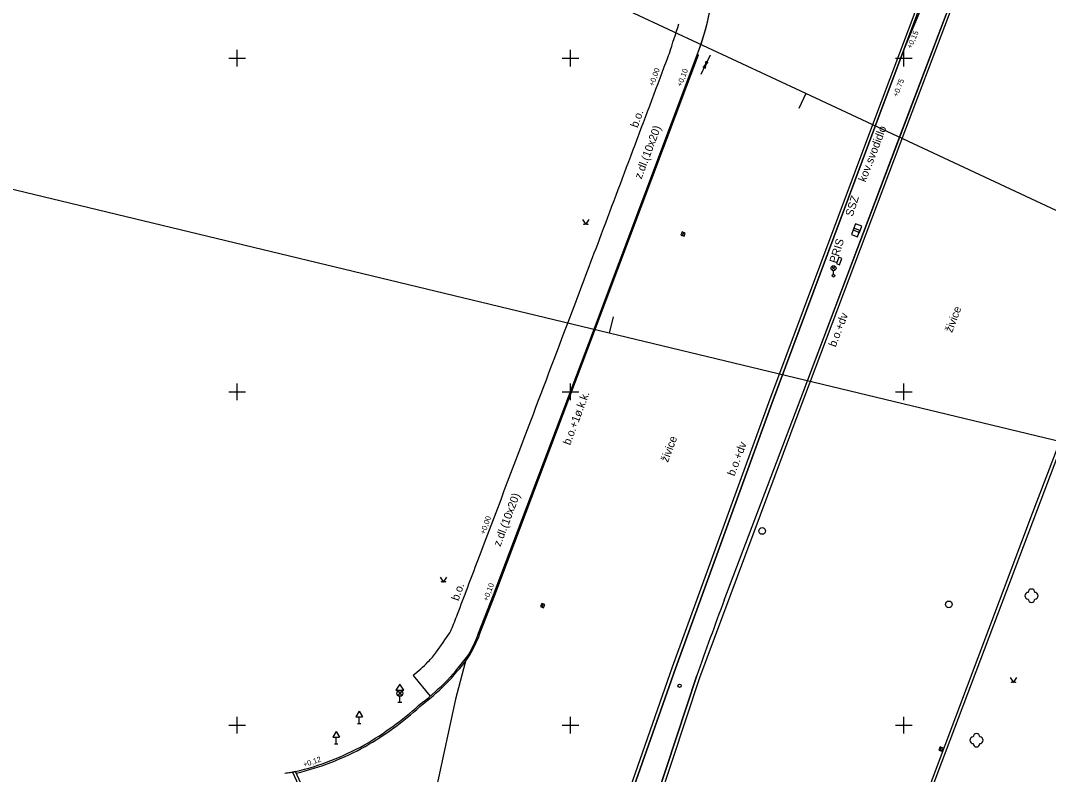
# Model space of a CAD drawing. Extents: x -599151 to -598424, y -1163476 to -1161924.
# Drawn here: x -598766.2 to -598689.2, y -1162728.7 to -1162672.2 of the extents above; entities that cross this region are included whole.
import ezdxf

# ---------------------------------------------------------------- set-up
doc = ezdxf.new("R2010")
doc.units = 0
for name, color, linetype in [('Vrstva 1', 7, 'Continuous'), ('Vrstva 14', 7, 'Continuous'), ('Vrstva 19', 7, 'Continuous'), ('Vrstva 21', 7, 'Continuous'), ('Vrstva 23', 7, 'Continuous'), ('Vrstva 25', 7, 'Continuous'), ('Vrstva 29', 7, 'Continuous'), ('Vrstva 44', 7, 'Continuous'), ('Vrstva 49', 7, 'Continuous'), ('Vrstva 50', 7, 'Continuous'), ('Vrstva 62', 7, 'Continuous'), ('Vrstva 63', 7, 'Continuous'), ('Vrstva 7', 7, 'Continuous')]:
    doc.layers.add(name, color=color, linetype=linetype)

msp = doc.modelspace()

# ---------------------------------------------------------------- linework, layer by layer
at = {"layer": 'Vrstva 1'}
for p, q in [((-598707.361, -1162677.641), (-598774.638, -1162646.226)), ((-598707.361, -1162677.641), (-598707.89, -1162678.774)), ((-598640.084, -1162709.057), (-598707.36, -1162677.641)), ((-598722.107, -1162695.603), (-598794.299, -1162678.242)), ((-598721.815, -1162694.387), (-598722.107, -1162695.603)), ((-598649.916, -1162712.964), (-598722.107, -1162695.603))]:
    msp.add_line(p, q, dxfattribs=at)
at = {"layer": 'Vrstva 14'}
for points in [[(-598724.104, -1162687.095), (-598723.854, -1162687.47), (-598723.604, -1162687.095)], [(-598734.771, -1162713.895), (-598734.521, -1162714.27), (-598734.271, -1162713.895)], [(-598692.032, -1162721.429), (-598691.782, -1162721.804), (-598691.532, -1162721.429)]]:
    msp.add_lwpolyline(points, dxfattribs=at)
for centre, radius in [((-598723.979, -1162687.445), 0.025), ((-598723.729, -1162687.445), 0.025), ((-598734.646, -1162714.245), 0.025), ((-598734.396, -1162714.245), 0.025), ((-598690.43, -1162715.29), 0.00025), ((-598691.907, -1162721.779), 0.025), ((-598691.657, -1162721.779), 0.025), ((-598694.56, -1162726.131), 0.00025)]:
    msp.add_circle(centre, radius, dxfattribs=at)
for centre, start, end in [((-598690.68, -1162715.29), 89.99999, 269.99999), ((-598690.43, -1162715.04), 0, 179.99999), ((-598690.18, -1162715.29), 270, 89.99999), ((-598690.43, -1162715.54), 179.99999, 359.99999), ((-598694.81, -1162726.131), 89.99999, 269.99999), ((-598694.56, -1162725.881), 0, 179.99999), ((-598694.31, -1162726.131), 270, 89.99999), ((-598694.56, -1162726.381), 179.99999, 359.99999)]:
    msp.add_arc(centre, 0.25, start, end, dxfattribs=at)
at = {"layer": 'Vrstva 19'}
for p, q in [((-598740.85, -1162723.938), (-598741.1, -1162724.371)), ((-598741.1, -1162724.371), (-598740.6, -1162724.371)), ((-598740.85, -1162723.938), (-598740.6, -1162724.371)), ((-598740.85, -1162724.871), (-598740.85, -1162724.371)), ((-598740.975, -1162724.871), (-598740.725, -1162724.871)), ((-598742.58, -1162725.468), (-598742.83, -1162725.901)), ((-598742.83, -1162725.901), (-598742.33, -1162725.901)), ((-598742.58, -1162725.468), (-598742.33, -1162725.901)), ((-598742.58, -1162726.401), (-598742.58, -1162725.901)), ((-598742.705, -1162726.401), (-598742.455, -1162726.401))]:
    msp.add_line(p, q, dxfattribs=at)
at = {"layer": 'Vrstva 21'}
msp.add_lwpolyline([(-598695.78, -1162664.24), (-598699.97, -1162674.3), (-598702.11, -1162679.97), (-598709.91, -1162700.89), (-598717.13, -1162720.74), (-598723.5, -1162738.84), (-598727.94, -1162752.59), (-598729.98, -1162757.92), (-598744.45, -1162796.07), (-598751.7, -1162815.01), (-598765.52, -1162851.41), (-598773.26, -1162871.58), (-598779.91, -1162889.88), (-598781.91, -1162894.82), (-598784.85, -1162901.68), (-598795.29, -1162929.3), (-598803.04, -1162949.86), (-598814.6, -1162980.19)], dxfattribs=at)
at = {"layer": 'Vrstva 23'}
for p, q in [((-598703.624, -1162687.407), (-598703.803, -1162687.874)), ((-598703.157, -1162687.586), (-598703.624, -1162687.407)), ((-598703.764, -1162687.737), (-598703.943, -1162688.204)), ((-598703.943, -1162688.204), (-598703.476, -1162688.383)), ((-598703.803, -1162687.874), (-598703.336, -1162688.053)), ((-598703.297, -1162687.916), (-598703.764, -1162687.737)), ((-598703.476, -1162688.383), (-598703.297, -1162687.916)), ((-598703.336, -1162688.053), (-598703.157, -1162687.586))]:
    msp.add_line(p, q, dxfattribs=at)
msp.add_circle((-598716.82, -1162722.04), 0.125, dxfattribs=at)
at = {"layer": 'Vrstva 25'}
for p, q in [((-598716.604, -1162688.297), (-598716.516, -1162688.063)), ((-598727.134, -1162716.147), (-598727.046, -1162715.913)), ((-598697.265, -1162726.907), (-598697.175, -1162726.673))]:
    msp.add_line(p, q, dxfattribs=at)
for points in [[(-598716.487, -1162688.341), (-598716.399, -1162688.107), (-598716.633, -1162688.019), (-598716.721, -1162688.253)], [(-598727.017, -1162716.191), (-598726.929, -1162715.957), (-598727.163, -1162715.869), (-598727.251, -1162716.103)], [(-598697.148, -1162726.951), (-598697.059, -1162726.718), (-598697.292, -1162726.629), (-598697.381, -1162726.862)], [(-598741.558, -1162737.828), (-598741.4, -1162737.681), (-598745.63, -1162728.471), (-598745.836, -1162728.513)]]:
    msp.add_lwpolyline(points, close=True, dxfattribs=at)
for centre in [(-598710.63, -1162710.44), (-598696.64, -1162715.94)]:
    msp.add_circle(centre, 0.25, dxfattribs=at)
at = {"layer": 'Vrstva 29'}
for p, q in [((-598705.412, -1162690.869), (-598705.148, -1162690.605)), ((-598705.144, -1162690.868), (-598705.408, -1162690.603)), ((-598705.28, -1162691.2), (-598705.28, -1162690.925))]:
    msp.add_line(p, q, dxfattribs=at)
msp.add_lwpolyline([(-598704.832, -1162690.478), (-598704.654, -1162690.011), (-598704.888, -1162689.922), (-598705.066, -1162690.389)], close=True, dxfattribs=at)
for centre, radius in [((-598705.28, -1162690.738), 0.188), ((-598705.28, -1162691.3), 0.1)]:
    msp.add_circle(centre, radius, dxfattribs=at)
at = {"layer": 'Vrstva 44'}
for p, q in [((-598737.65, -1162722.43), (-598737.95, -1162722.774)), ((-598737.95, -1162722.43), (-598737.65, -1162722.774)), ((-598737.8, -1162723.28), (-598737.8, -1162722.83)), ((-598737.95, -1162723.28), (-598737.65, -1162723.28))]:
    msp.add_line(p, q, dxfattribs=at)
msp.add_lwpolyline([(-598738.1, -1162722.374), (-598737.5, -1162722.374), (-598737.8, -1162721.924), (-598738.1, -1162722.374)], dxfattribs=at)
msp.add_circle((-598737.8, -1162722.602), 0.228, dxfattribs=at)
at = {"layer": 'Vrstva 49'}
for p, q in [((-598714.54, -1162674.763), (-598714.869, -1162675.483)), ((-598715.198, -1162676.203), (-598714.869, -1162675.483)), ((-598715.046, -1162675.697), (-598714.869, -1162675.483)), ((-598714.869, -1162675.483), (-598714.915, -1162675.759)), ((-598714.869, -1162675.483), (-598714.824, -1162675.207)), ((-598714.692, -1162675.267), (-598714.869, -1162675.483))]:
    msp.add_line(p, q, dxfattribs=at)
at = {"layer": 'Vrstva 62'}
for p, q in [((-598750.625, -1162675), (-598749.375, -1162675)), ((-598750, -1162675.625), (-598750, -1162674.375)), ((-598725.625, -1162675), (-598724.375, -1162675)), ((-598725, -1162675.625), (-598725, -1162674.375)), ((-598700.625, -1162675), (-598699.375, -1162675)), ((-598700, -1162675.625), (-598700, -1162674.375)), ((-598750, -1162700.625), (-598750, -1162699.375)), ((-598725, -1162700.625), (-598725, -1162699.375)), ((-598700, -1162700.625), (-598700, -1162699.375)), ((-598750.625, -1162700), (-598749.375, -1162700)), ((-598725.625, -1162700), (-598724.375, -1162700)), ((-598700.625, -1162700), (-598699.375, -1162700)), ((-598750, -1162725.625), (-598750, -1162724.375)), ((-598725, -1162725.625), (-598725, -1162724.375)), ((-598700, -1162725.625), (-598700, -1162724.375)), ((-598750.625, -1162725), (-598749.375, -1162725)), ((-598725.625, -1162725), (-598724.375, -1162725)), ((-598700.625, -1162725), (-598699.375, -1162725))]:
    msp.add_line(p, q, dxfattribs=at)
at = {"layer": 'Vrstva 63'}
for points in [[(-598859.45, -1163096.65), (-598854.32, -1163084.15), (-598824.47, -1163005.5), (-598816.67, -1162984.98), (-598803.24, -1162949.74), (-598780.23, -1162889.28), (-598773.478, -1162871.463), (-598765.88, -1162851.33), (-598758.84, -1162832.8), (-598745.6, -1162798.16), (-598737.25, -1162776.15), (-598728.25, -1162752.5), (-598723.5, -1162738.84), (-598717.13, -1162720.74), (-598709.91, -1162700.89), (-598702.11, -1162679.97), (-598696.15, -1162664.13), (-598695.39, -1162662.07), (-598693.97, -1162658.31)], [(-598713.47, -1162715.62), (-598708.12, -1162701.56), (-598694.22, -1162664.8), (-598692.03, -1162658.97)], [(-598731.89, -1162718.09), (-598730.78, -1162715.22), (-598723.28, -1162695.43), (-598715.5, -1162674.74)], [(-598697.52, -1162728.69), (-598683.522, -1162691.742)], [(-598732.8, -1162719.93), (-598733.62, -1162723.04), (-598736.975, -1162738.546)], [(-598715.54, -1162721.28), (-598721.7, -1162739.99), (-598727.72, -1162758.34), (-598733.31, -1162775.48), (-598734.01, -1162777.52), (-598762.71, -1162852.94), (-598770.32, -1162872.91), (-598777.27, -1162891.31), (-598784.14, -1162909.43), (-598799.74, -1162950.34), (-598813.33, -1162986.07), (-598821.23, -1163006.93), (-598828.55, -1163026.09), (-598835.89, -1163045.37), (-598843.55, -1163065.41), (-598852.18, -1163085.13), (-598858.28, -1163096.77)]]:
    msp.add_lwpolyline(points, dxfattribs=at)
for centre, radius, start, end in [((-598733.303, -1162667.848), 19.091, 338.83707, 2.45527), ((-598468.093, -1162808.569), 262.391, 159.2533, 160.56931), ((-598739.805, -1162715.321), 8.385, 326.65376, 340.71545), ((-598851.716, -1162677.132), 162.587, 335.66863, 341.51174)]:
    msp.add_arc(centre, radius, start, end, dxfattribs=at)
at = {"layer": 'Vrstva 7'}
msp.add_line((-598736.81, -1162721.261), (-598735.53, -1162722.821), dxfattribs=at)
for points in [[(-598696.37, -1162664.06), (-598702.36, -1162680), (-598710.16, -1162700.82), (-598717.38, -1162720.66), (-598723.7, -1162738.77), (-598728.46, -1162752.352), (-598730.54, -1162757.75), (-598737.46, -1162776.08), (-598745, -1162795.86), (-598752.22, -1162814.82), (-598759.04, -1162832.74), (-598766.06, -1162851.25)], [(-598765.88, -1162851.33), (-598758.84, -1162832.8), (-598752, -1162814.9), (-598745.6, -1162798.16), (-598744.77, -1162795.95), (-598742.6, -1162790.26), (-598740.02, -1162783.45), (-598737.25, -1162776.15), (-598730.28, -1162757.84), (-598728.25, -1162752.5), (-598723.5, -1162738.84), (-598717.13, -1162720.74), (-598709.91, -1162700.89), (-598702.11, -1162679.97), (-598699.97, -1162674.3), (-598696.15, -1162664.13)], [(-598762.5, -1162853.02), (-598755.36, -1162834.29), (-598748.57, -1162816.46), (-598741.19, -1162797.06), (-598733.81, -1162777.57), (-598727.52, -1162758.45), (-598721.48, -1162740.08), (-598715.31, -1162721.42), (-598707.94, -1162701.65), (-598699.86, -1162680.28), (-598694, -1162664.87)], [(-598713.47, -1162715.62), (-598708.12, -1162701.56), (-598700.05, -1162680.2), (-598694.22, -1162664.8)], [(-598731.89, -1162718.09), (-598730.78, -1162715.22), (-598723.28, -1162695.43), (-598715.5, -1162674.74)], [(-598731.796, -1162718.123), (-598730.67, -1162715.26), (-598723.19, -1162695.47), (-598715.398, -1162674.748)], [(-598715.489, -1162674.713), (-598715.398, -1162674.748)], [(-598697.52, -1162728.69), (-598683.522, -1162691.742)], [(-598690.36, -1162709.11), (-598686.141, -1162698.089), (-598683.709, -1162691.671)], [(-598697.72, -1162728.61), (-598690.36, -1162709.11)], [(-598762.71, -1162852.94), (-598755.58, -1162834.21), (-598748.79, -1162816.36), (-598741.41, -1162796.99), (-598734.01, -1162777.52), (-598733.31, -1162775.48), (-598727.72, -1162758.34), (-598721.7, -1162739.99), (-598715.54, -1162721.28)]]:
    msp.add_lwpolyline(points, dxfattribs=at)
for centre, radius, start, end in [((-598733.303, -1162667.848), 19.091, 338.83707, 19.61216), ((-599138.699, -1162537.655), 442.83, 341.98023, 342.28361), ((-598730.65, -1162670.081), 13.834, 338.15233, 340.75068), ((-604922.734, -1160348.844), 6626.7, 339.3242528, 339.4476917), ((-602032.012, -1161439.362), 3537.12, 339.225531, 339.318242), ((-604724.059, -1160427.97), 6412.878, 339.2290639, 339.3077972), ((-707912.056, -1121295.574), 116771.871, 339.22594444, 339.23143333), ((-599379.184, -1162469.033), 691.565, 339.017439, 339.374089), ((-598468.093, -1162808.569), 262.391, 159.2533, 160.56931), ((-598847.823, -1162672.904), 122.435, 338.45792, 339.05488), ((-598783.884, -1162684.336), 60.177, 324.24313, 325.90871), ((-598734.93, -1162717.47), 1.064, 325.90871, 338.45792), ((-598739.805, -1162715.321), 8.385, 326.65376, 340.71545), ((-598739.805, -1162715.321), 8.485, 326.63308, 340.71545), ((-598740.034, -1162715.911), 6.142, 315, 324.24313), ((-598745.726, -1162710.219), 14.192, 308.92299, 315), ((-598747.048, -1162709.252), 17.806, 306.84952, 323.15048), ((-598747.108, -1162709.332), 17.906, 307.16858, 323.47931), ((-598752.43, -1162705.721), 23.959, 299.99821, 312.09328), ((-598752.423, -1162705.749), 24.061, 300.01166, 312.10582), ((-598750.062, -1162709.29), 19.686, 283.0129, 299.22291), ((-598750.062, -1162709.29), 19.816, 283.09043, 299.22291), ((-598749.257, -1162704.118), 24.637, 276.62742, 277.53944), ((-598746.576, -1162724.378), 4.2, 277.53944, 283.01291), ((-598851.826, -1162677.087), 162.491, 335.67015, 341.51326)]:
    msp.add_arc(centre, radius, start, end, dxfattribs=at)

# ---------------------------------------------------------------- texts
at = {"layer": 'Vrstva 49'}
for s, height, rotation, p in [('b.o.', 0.6, 70.36395, (-598719.97, -1162680.253)), ('z.dl.(10x20)', 0.6, 69.28184, (-598719.685, -1162684.101)), ('kov.svodidlo', 0.59996, 68.93102, (-598702.884, -1162684.325)), ('SSZ', 0.6, 72.37198, (-598703.839, -1162686.903)), ('PRIS', 0.6, 72.31819, (-598705.047, -1162690.417)), ('živice', 0.6, 69.17099, (-598696.394, -1162695.612)), ('b.o.+dv', 0.6, 69.19009, (-598705.115, -1162696.697)), ('b.o.+1ø.k.k.', 0.6, 69.56538, (-598725.033, -1162704.046)), ('živice', 0.6, 69.17099, (-598717.701, -1162705.332)), ('b.o.+dv', 0.6, 69.19009, (-598712.718, -1162706.369)), ('z.dl.(10x20)', 0.6, 69.28184, (-598730.261, -1162711.65)), ('b.o.', 0.6, 70.36395, (-598733.406, -1162715.717))]:
    msp.add_text(s, height=height, rotation=rotation, dxfattribs=at).set_placement(p)
at = {"layer": 'Vrstva 50'}
for s, rotation, p in [('+0,15', 66.6373, (-598699.439, -1162674.321)), ('+0,00', 70.36395, (-598718.765, -1162677.134)), ('+0,10', 69.39238, (-598716.674, -1162677.176)), ('+0.75', 69.11223, (-598700.471, -1162677.937)), ('+0,00', 70.36395, (-598731.416, -1162710.717)), ('+0,10', 69.39238, (-598731.211, -1162715.738)), ('+0,12', 19.31899, (-598744.974, -1162728.165))]:
    msp.add_text(s, height=0.4, rotation=rotation, dxfattribs=at).set_placement(p)

doc.saveas('drawing.dxf')
